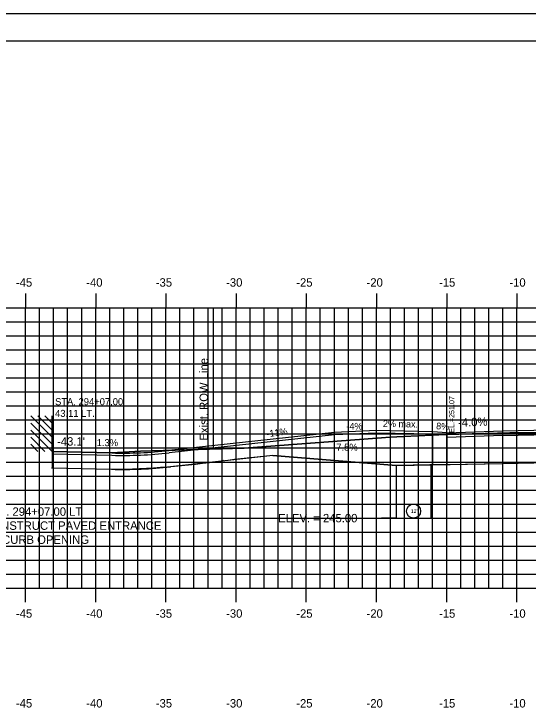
# Model space of a CAD drawing. Extents: x 859129 to 859299, y 366268 to 366378.
# Drawn here: x 859166.64 to 859203.26, y 366328.48 to 366378.18 of the extents above; entities that cross this region are included whole.
import ezdxf

# ---------------------------------------------------------------- set-up
doc = ezdxf.new("R2010")
doc.units = 0
for name, color, linetype in [('ANNOTATION', 7, 'Continuous'), ('BORDER', 7, 'Continuous'), ('D_Roadway_Drive_Gravel_LT', 7, 'Continuous'), ('D_Roadway_Drive_SubGrade', 7, 'Continuous'), ('D_Roadway_Edge_Shoulder', 7, 'Continuous'), ('D_Roadway_SubGrade', 7, 'Continuous'), ('D_Text_Monospaced', 7, 'Continuous'), ('D_Text_Standard', 7, 'Continuous'), ('E_ROW_Line', 7, 'Continuous'), ('H_V ANNOTATION', 7, 'Continuous'), ('JUNK COM EXC', 7, 'Continuous'), ('junk strct exc', 7, 'Continuous'), ('MAJOR', 7, 'Continuous'), ('MINOR', 7, 'Continuous'), ('PDRAIN', 7, 'Continuous'), ('PLOT BOUNDARY', 7, 'Continuous'), ('S_Buildings', 7, 'Continuous'), ('S_Roadway_Centerline', 7, 'Continuous'), ('TEXT', 7, 'Continuous')]:
    doc.layers.add(name, color=color, linetype=linetype)

msp = doc.modelspace()

# ---------------------------------------------------------------- linework, layer by layer
at = {"layer": 'ANNOTATION'}
msp.add_line((859189.48, 366348.185), (859177.685, 366346.887), dxfattribs=at)
msp.add_arc((859174.387, 366376.873), 30, 268.5198, 276.2773, dxfattribs=at)
at = {"layer": 'BORDER'}
msp.add_line((859297.462, 366376.236), (859137.462, 366376.236), dxfattribs=at)
at = {"layer": 'D_Roadway_Drive_Gravel_LT'}
for p, q in [((859189.462, 366348.35), (859177.667, 366347.053)), ((859192.466, 366348.471), (859189.462, 366348.35)), ((859192.473, 366348.304), (859189.462, 366348.184)), ((859196.458, 366348.224), (859192.458, 366348.304)), ((859196.466, 366348.391), (859192.466, 366348.471)), ((859197.462, 366348.144), (859196.458, 366348.224)), ((859197.466, 366348.311), (859196.466, 366348.391)), ((859197.466, 366348.311), (859197.462, 366347.977)), ((859169.349, 366346.827), (859173.607, 366346.717)), ((859185.083, 366346.695), (859177.794, 366345.893)), ((859169.323, 366345.827), (859173.582, 366345.717))]:
    msp.add_line(p, q, dxfattribs=at)
msp.add_lwpolyline([(859169.353, 366346.993), (859173.612, 366346.883)], dxfattribs=at)
for radius in [30.167, 31.167]:
    msp.add_arc((859174.387, 366376.873), radius, 268.5198, 276.2773, dxfattribs=at)
at = {"layer": 'D_Roadway_Drive_SubGrade'}
for p, q in [((859169.353, 366346.993), (859169.353, 366345.827)), ((859193.855, 366345.985), (859185.083, 366346.695)), ((859197.462, 366346.057), (859193.855, 366345.985))]:
    msp.add_line(p, q, dxfattribs=at)
at = {"layer": 'D_Roadway_Edge_Shoulder'}
msp.add_lwpolyline([(859197.466, 366348.311), (859201.462, 366348.47), (859212.462, 366348.69), (859223.462, 366348.47), (859227.464, 366348.311)], dxfattribs=at)
at = {"layer": 'D_Roadway_SubGrade'}
for points in [[(859201.462, 366348.137), (859197.462, 366347.977), (859197.462, 366346.057), (859201.462, 366346.137)], [(859201.462, 366346.137), (859201.462, 366348.137), (859212.462, 366348.357), (859223.462, 366348.137), (859223.462, 366346.137), (859212.462, 366346.357)]]:
    msp.add_lwpolyline(points, close=True, dxfattribs=at)
at = {"layer": 'D_Text_Standard'}
msp.add_lwpolyline([(859193.855, 366342.236), (859193.509, 366342.236), (859192.829, 366342.236)], dxfattribs=at)
at = {"layer": 'E_ROW_Line'}
msp.add_line((859180.861, 366347.165), (859180.861, 366357.165), dxfattribs=at)
at = {"layer": 'JUNK COM EXC'}
for points in [[(859196.462, 366348.151), (859196.462, 366346.037), (859201.462, 366346.137), (859212.462, 366346.357), (859223.462, 366346.137), (859228.464, 366346.037), (859228.466, 366348.614), (859227.539, 366348.481), (859226.052, 366348.278), (859225.954, 366348.264), (859225.274, 366348.251), (859225.106, 366348.22), (859222.892, 366348.262), (859222.456, 366348.252), (859214.703, 366348.376), (859213.255, 366348.415), (859210.867, 366348.383), (859201.956, 366348.308), (859200.211, 366348.266), (859197.405, 366348.194), (859196.462, 366348.151)], [(859185.083, 366346.695), (859193.855, 366345.985), (859196.462, 366346.037), (859196.462, 366348.151), (859193.405, 366348.01), (859192.828, 366347.969), (859183.025, 366347.23), (859175.658, 366347.011), (859173.61, 366346.883), (859169.353, 366346.993), (859169.353, 366345.827), (859173.582, 366345.717)], [(859181.56, 366346.337), (859181.439, 366346.294)]]:
    msp.add_lwpolyline(points, dxfattribs=at)
for centre, radius, start, end in [((859193.448, 366253.887), 93.184, 95.15005, 97.40455), ((859172.781, 366407.658), 61.946, 270.74041, 278.14713)]:
    msp.add_arc(centre, radius, start, end, dxfattribs=at)
at = {"layer": 'junk strct exc'}
msp.add_lwpolyline([(859193.855, 366345.985), (859193.855, 366342.236), (859196.355, 366342.236), (859196.355, 366346.035)], close=True, dxfattribs=at)
at = {"layer": 'MAJOR'}
for p, q in [((859167.462, 366358.238), (859167.462, 366357.236)), ((859172.462, 366358.238), (859172.462, 366357.236)), ((859177.462, 366358.238), (859177.462, 366357.236)), ((859182.462, 366358.238), (859182.462, 366357.236)), ((859187.462, 366358.238), (859187.462, 366357.236)), ((859192.462, 366358.238), (859192.462, 366357.236)), ((859197.462, 366358.238), (859197.462, 366357.236)), ((859202.462, 366358.238), (859202.462, 366357.236)), ((859142.462, 366357.236), (859282.462, 366357.236)), ((859142.462, 366357.236), (859282.462, 366357.236)), ((859167.462, 366337.236), (859167.462, 366357.236)), ((859172.462, 366337.236), (859172.462, 366357.236)), ((859177.462, 366337.236), (859177.462, 366357.236)), ((859182.462, 366337.236), (859182.462, 366357.236)), ((859187.462, 366337.236), (859187.462, 366357.236)), ((859192.462, 366337.236), (859192.462, 366357.236)), ((859197.462, 366337.236), (859197.462, 366357.236)), ((859202.462, 366337.236), (859202.462, 366357.236)), ((859142.462, 366352.236), (859282.462, 366352.236)), ((859142.462, 366347.236), (859282.462, 366347.236)), ((859142.462, 366342.236), (859282.462, 366342.236)), ((859142.462, 366337.236), (859282.462, 366337.236)), ((859142.462, 366337.236), (859282.462, 366337.236)), ((859167.462, 366336.234), (859167.462, 366337.236)), ((859172.462, 366336.234), (859172.462, 366337.236)), ((859177.462, 366336.234), (859177.462, 366337.236)), ((859182.462, 366336.234), (859182.462, 366337.236)), ((859187.462, 366336.234), (859187.462, 366337.236)), ((859192.462, 366336.234), (859192.462, 366337.236)), ((859197.462, 366336.234), (859197.462, 366337.236)), ((859202.462, 366336.234), (859202.462, 366337.236))]:
    msp.add_line(p, q, dxfattribs=at)
at = {"layer": 'MINOR'}
for p, q in [((859168.462, 366337.236), (859168.462, 366357.236)), ((859169.462, 366337.236), (859169.462, 366357.236)), ((859170.462, 366337.236), (859170.462, 366357.236)), ((859171.462, 366337.236), (859171.462, 366357.236)), ((859173.462, 366337.236), (859173.462, 366357.236)), ((859174.462, 366337.236), (859174.462, 366357.236)), ((859175.462, 366337.236), (859175.462, 366357.236)), ((859176.462, 366337.236), (859176.462, 366357.236)), ((859178.462, 366337.236), (859178.462, 366357.236)), ((859179.462, 366337.236), (859179.462, 366357.236)), ((859180.462, 366337.236), (859180.462, 366357.236)), ((859181.462, 366337.236), (859181.462, 366357.236)), ((859183.462, 366337.236), (859183.462, 366357.236)), ((859184.462, 366337.236), (859184.462, 366357.236)), ((859185.462, 366337.236), (859185.462, 366357.236)), ((859186.462, 366337.236), (859186.462, 366357.236)), ((859188.462, 366337.236), (859188.462, 366357.236)), ((859189.462, 366337.236), (859189.462, 366357.236)), ((859190.462, 366337.236), (859190.462, 366357.236)), ((859191.462, 366337.236), (859191.462, 366357.236)), ((859193.462, 366337.236), (859193.462, 366357.236)), ((859194.462, 366337.236), (859194.462, 366357.236)), ((859195.462, 366337.236), (859195.462, 366357.236)), ((859196.462, 366337.236), (859196.462, 366357.236)), ((859198.462, 366337.236), (859198.462, 366357.236)), ((859199.462, 366337.236), (859199.462, 366357.236)), ((859200.462, 366337.236), (859200.462, 366357.236)), ((859201.462, 366337.236), (859201.462, 366357.236)), ((859142.462, 366356.236), (859282.462, 366356.236)), ((859142.462, 366355.236), (859282.462, 366355.236)), ((859142.462, 366354.236), (859282.462, 366354.236)), ((859142.462, 366353.236), (859282.462, 366353.236)), ((859142.462, 366351.236), (859282.462, 366351.236)), ((859142.462, 366350.236), (859282.462, 366350.236)), ((859142.462, 366349.236), (859282.462, 366349.236)), ((859142.462, 366348.236), (859282.462, 366348.236)), ((859142.462, 366346.236), (859282.462, 366346.236)), ((859142.462, 366345.236), (859282.462, 366345.236)), ((859142.462, 366344.236), (859282.462, 366344.236)), ((859142.462, 366343.236), (859282.462, 366343.236)), ((859142.462, 366341.236), (859282.462, 366341.236)), ((859142.462, 366340.236), (859282.462, 366340.236)), ((859142.462, 366339.236), (859282.462, 366339.236)), ((859142.462, 366338.236), (859282.462, 366338.236))]:
    msp.add_line(p, q, dxfattribs=at)
at = {"layer": 'PDRAIN'}
msp.add_lwpolyline([(859193.855, 366345.985), (859193.855, 366342.236), (859196.355, 366342.236), (859196.355, 366346.035)], dxfattribs=at)
msp.add_circle((859195.105, 366342.736), 0.5, dxfattribs=at)
at = {"layer": 'PLOT BOUNDARY'}
msp.add_lwpolyline([(859129.368, 366268.177), (859299.368, 366268.177), (859299.368, 366378.177), (859129.368, 366378.177)], close=True, dxfattribs=at)
at = {"layer": 'S_Buildings'}
for p, q in [((859169.353, 366348.01), (859167.844, 366349.519)), ((859169.353, 366348.502), (859168.336, 366349.519)), ((859169.353, 366348.994), (859168.828, 366349.519)), ((859169.353, 366346.993), (859169.353, 366349.519)), ((859169.353, 366347.518), (859167.844, 366348.994)), ((859169.353, 366346.993), (859167.844, 366348.502)), ((859168.828, 366346.993), (859167.844, 366348.01)), ((859168.336, 366346.993), (859167.844, 366347.518))]:
    msp.add_line(p, q, dxfattribs=at)
at = {"layer": 'S_Roadway_Centerline'}
msp.add_lwpolyline([(859169.353, 366346.993), (859173.61, 366346.883), (859175.658, 366347.011), (859183.025, 366347.23), (859192.828, 366347.969), (859193.405, 366348.01), (859197.405, 366348.194), (859200.211, 366348.266), (859201.956, 366348.308), (859210.867, 366348.383), (859213.255, 366348.415), (859214.703, 366348.376), (859222.456, 366348.252), (859222.892, 366348.262), (859225.106, 366348.22), (859225.274, 366348.251), (859225.954, 366348.264), (859226.052, 366348.278), (859227.539, 366348.481), (859228.478, 366348.616), (859228.625, 366348.643), (859229.051, 366348.623), (859249.622, 366347.669)], dxfattribs=at)

# ---------------------------------------------------------------- texts
at = {"layer": 'ANNOTATION'}
msp.add_text('-4.0%', height=0.6, rotation=2.2906, dxfattribs=at).set_placement((859198.282, 366348.744))
for s, p in [('STA. 294+07.00 LT', (859164.526, 366342.403)), ('CONSTRUCT PAVED ENTRANCE', (859164.526, 366341.403)), ("26' CURB OPENING", (859164.526, 366340.403))]:
    msp.add_text(s, height=0.6, dxfattribs=at).set_placement(p)
at = {"layer": 'D_Roadway_Drive_Gravel_LT'}
msp.add_text('-4%', height=0.48, dxfattribs=at).set_placement((859190.321, 366348.547))
for s, rotation, p in [('2% max.', 358.8078, (859192.92, 366348.741)), ('8%', 355.4261, (859196.697, 366348.578)), ('-11%', 7.7924, (859184.663, 366347.999))]:
    msp.add_text(s, height=0.48, rotation=rotation, dxfattribs=at).set_placement(p)
at = {"layer": 'D_Text_Monospaced'}
for s, height, p in [('STA. 294+07.00', 0.49998, (859169.568, 366350.288)), ('43.11 LT.', 0.5, (859169.568, 366349.454))]:
    msp.add_text(s, height=height, dxfattribs=at).set_placement(p)
at = {"layer": 'D_Text_Standard'}
msp.add_text(' EL.=251.07', height=0.36848, rotation=90, dxfattribs=at).set_placement((859198.005, 366348.175))
for s, p in [("-43.1'", (859169.709, 366347.404)), ('ELEV. = 245.00', (859185.46, 366341.936))]:
    msp.add_text(s, height=0.6, dxfattribs=at).set_placement(p)
at = {"layer": 'E_ROW_Line'}
msp.add_text('Exist. ROW Line', height=0.6, rotation=90, dxfattribs=at).set_placement((859180.461, 366347.765))
at = {"layer": 'H_V ANNOTATION'}
for s, p in [('-45', (859166.779, 366358.736)), ('-40', (859171.787, 366358.736)), ('-35', (859176.742, 366358.736)), ('-30', (859181.75, 366358.736)), ('-25', (859186.747, 366358.736)), ('-20', (859191.755, 366358.736)), ('-15', (859196.918, 366358.736)), ('-10', (859201.927, 366358.736)), ('-45', (859166.779, 366335.136)), ('-40', (859171.787, 366335.136)), ('-35', (859176.742, 366335.136)), ('-30', (859181.75, 366335.136)), ('-25', (859186.747, 366335.136)), ('-20', (859191.755, 366335.136)), ('-15', (859196.918, 366335.136)), ('-10', (859201.927, 366335.136)), ('-45', (859166.779, 366328.736)), ('-40', (859171.787, 366328.736)), ('-35', (859176.742, 366328.736)), ('-30', (859181.75, 366328.736)), ('-25', (859186.747, 366328.736)), ('-20', (859191.755, 366328.736)), ('-15', (859196.918, 366328.736)), ('-10', (859201.927, 366328.736))]:
    msp.add_text(s, height=0.6, dxfattribs=at).set_placement(p)
at = {"layer": 'PDRAIN'}
msp.add_text('12"', height=0.25, dxfattribs=at).set_placement((859194.914, 366342.612))
at = {"layer": 'TEXT'}
for s, p in [('1.3%', (859172.531, 366347.367)), ('7.5%', (859189.601, 366347.044))]:
    msp.add_text(s, height=0.5, dxfattribs=at).set_placement(p)

doc.saveas('drawing.dxf')
